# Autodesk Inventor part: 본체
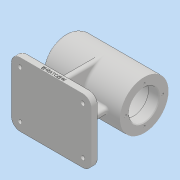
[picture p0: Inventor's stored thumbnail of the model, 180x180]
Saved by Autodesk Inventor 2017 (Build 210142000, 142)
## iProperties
Part Number: 본체
Material: 일반
Document SubType Name: Modeling
Designer: mrc
Density: 1 g/cm^3
Appearance: 기본값
Author: mrc
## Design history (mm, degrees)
sketch "스케치1"
  geometry: L1 (-56, 0)-(56, 0); L2 (-56, 0)-(-56, 34); L3 (-56, 34)-(56, 34); L4 (56, 34)-(56, 21); L5 (56, 21)-(41, 21); L6 (41, 21)-(41, 24); L7 (41, 24)-(-13, 24); L8 (-13, 24)-(-13, 21); L9 (-13, 21)-(-25, 21); L10 (-25, 21)-(-25, 17.5); L11 (-25, 17.5)-(-43, 17.5); L12 (-43, 17.5)-(-43, 16); L13 (-43, 16)-(-47, 16); L14 (-47, 16)-(-47, 10.5); L15 (-47, 10.5)-(-50, 10.5); L16 (-50, 10.5)-(-50, 0); 2 further points
  constraints: 32 end point, 14 perpendicular, 2 midpoint, 1 horizontal, 1 point on line, 1 vertical, 1 vertical alignment
  dimensions: "d0" = 68 diameter of L3 L1; "d1" = 112 distance between parallel lines of L4 L2; "d2" = 15 distance between parallel lines of L4 L6; "d3" = 54 distance between parallel lines of L8 L6; "d4" = 12 distance between parallel lines of L10 L8; "d5" = 18 distance between parallel lines of L12 L10; "d6" = 4 distance between parallel lines of L12 L14; "d7" = 3 distance between parallel lines of L16 L14; "d8" = 42 diameter of L5 L1; "d9" = 48 diameter of L7 L1; "d10" = 42 diameter of L9 L1; "d11" = 35 diameter of L11 L1; "d12" = 32 diameter of L13 L1; "d13" = 21 diameter of L15 L1
revolve "회전1" sketch "스케치1" stored, may be unused: angle "d14" = 90 deg
sketch "스케치3"
  geometry: 2 further points
  constraints: 1 vertical alignment
  dimensions: "d15" = 26 distance of point (0, 0) point (0, 26)
hole "구멍1" sketch "스케치3" at (0, 26) diameter "d16" = 3.242; stored, may be unused: countersink angle "d20" = 90 deg, drill point angle "d22" = 118 deg; dims "d17" = 8, "d18" = 4, "d19" = 2, "d21" = 11
node "작업 평면1"
sketch "스케치4"
  geometry: L1 (56, 45)-(-56, 45); L2 (-56, 45)-(-56, -45); L3 (-56, -45)-(56, -45); L4 (56, -45)-(56, 45); 3 further points
  constraints: 8 end point, 2 midpoint, 2 parallel, 1 horizontal, 1 horizontal alignment, 1 perpendicular, 1 vertical alignment
  dimensions: "d27" = 112 distance between parallel lines of L2 L4; "d28" = 90 distance between parallel lines of L3 L1
extrude "돌출1" join sketch "스케치4" distance "d29" = 10; taper "d30" = 0 deg
sketch "스케치5"
  geometry: L1 (-4, 34)-(4, 34); L2 (4, 34)-(4, -34); L3 (4, -34)-(-4, -34); L4 (-4, -34)-(-4, 34); L5 (-38, 4)-(38, 4); L6 (38, 4)-(38, -4); L7 (38, -4)-(-38, -4); L8 (-38, -4)-(-38, 4); L9 (56, -45)-(56, 45) reference; 5 further points
  constraints: 16 end point, 4 midpoint, 4 parallel, 2 horizontal, 2 horizontal alignment, 2 perpendicular, 2 vertical alignment
  dimensions: "d31" = 8 distance between parallel lines of L2 L4; "d32" = 8 distance between parallel lines of L7 L5; "d33" = 18 distance between parallel lines of L9 L6; "d34" = 68 distance between parallel lines of L3 L1
extrude "돌출2" join sketch "스케치5" stored distance "d35" = 10; taper "d36" = 0 deg
sketch "스케치6"
  geometry: L1 (112, 0)-(112, 10) reference; L2 (0, 0)-(112, 0) reference; 2 further points
  constraints: 1 other
  dimensions: "d37" = 56 distance from line of L1 point (56, 3); "d38" = 3 distance from line of L2 point (56, 3)
feature "엠보싱1" sketch "스케치6" dims "d39" = 0.5, "d40" = 0
fillet "모깎기1" dims "d41" = 12
sketch "스케치7"
  geometry: L1 (-56, 33)-(-56, -33) reference; L2 (44, 45)-(-44, 45) reference; L3 (56, -33)-(56, 33) reference; L4 (-44, -45)-(44, -45) reference; A1 r 12 centre (-44, -33) between (-56, -33) and (-44, -45) reference; A2 r 12 centre (-44, 33) between (-44, 45) and (-56, 33) reference; A3 r 12 centre (44, 33) between (56, 33) and (44, 45) reference; A4 r 12 centre (44, -33) between (44, -45) and (56, -33) reference; 5 further points
  constraints: 4 coincident
hole "구멍2" sketch "스케치7" at (-44, 33), (44, 33), (44, -33), (-44, -33) diameter "d42" = 5.5; stored, may be unused: countersink angle "d46" = 90 deg, drill point angle "d48" = 118 deg; dims "d43" = 8, "d44" = 9.5, "d45" = 5.4, "d47" = 11
chamfer "모따기1" distance "d49" = 1; stored, may be unused: second distance "d50" = 2, angle "d51" = 45 deg
fillet "모깎기2" dims "d52" = 3
fillet "모깎기3" dims "d53" = 3
fillet "모깎기4" dims "d54" = 0.3
fillet "모깎기5" dims "d55" = 3
fillet "모깎기6" dims "d56" = 3
fillet "모깎기7" dims "d57" = 3
fillet "모깎기8" dims "d58" = 3
fillet "모깎기9" dims "d59" = 3
fillet "모깎기10" dims "d60" = 10
fillet "모깎기11" dims "d61" = 3
node "솔리드1"
pattern_circular "원형 패턴1" dims angle "d24" = 360 deg
node "투영된 루프1"
other parameters: "d26" = -74
